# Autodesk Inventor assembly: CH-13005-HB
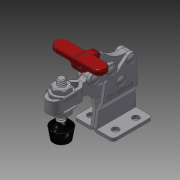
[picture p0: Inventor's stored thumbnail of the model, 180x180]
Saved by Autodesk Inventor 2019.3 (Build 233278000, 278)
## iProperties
Company: Î¢ÈíÖÐ¹ú
Created: 2012-09
Part Number: CH-13005-HB
Material: Ogólny
Description: STEP AP203
Document SubType Name: Assembly
Designer: CADENGINEERING4
Stock Number: DOCISK PIONOWY
Sending System: SolidWorks 2010
Preprocessor: SwSTEP 2.0
Title: CH-13005-HB.STEP
Author: Î¢ÈíÓÃ»§
Revision Number: ÈÎºÎ
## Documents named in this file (9)
- D:\Vault_2016\Projekty\Clamptek\STRONA\Vertical toggle clamp\CH-13005-HB\CH-13005-HB.iam
- D:\Vault_2016\Projekty\Clamptek\STRONA\Vertical toggle clamp\CH-13005-HB\CH-FW-100.ipt
- D:\Vault_2016\Projekty\Clamptek\STRONA\Vertical toggle clamp\CH-13005-HB\CH-13005-04 CONNECTING-PLATE.ipt
- D:\Vault_2016\Projekty\Clamptek\STRONA\Vertical toggle clamp\CH-13005-HB\CH-13005-05 .ipt
- D:\Vault_2016\Projekty\Clamptek\STRONA\Vertical toggle clamp\CH-13005-HB\CH-13005-02 U-BAR.ipt
- D:\Vault_2016\Projekty\Clamptek\STRONA\Vertical toggle clamp\CH-13005-HB\CH-FC-10138 Nut.ipt
- D:\Vault_2016\Projekty\Clamptek\STRONA\Vertical toggle clamp\CH-13005-HB\CH-13005-HB-01 FLANGED BASE.ipt
- D:\Vault_2016\Projekty\Clamptek\STRONA\Vertical toggle clamp\CH-13005-HB\CH-FC-10138 SPINDLE SUPPLIED.ipt
- D:\Vault_2016\Projekty\Clamptek\STRONA\Vertical toggle clamp\CH-13005-HB\CH-13005-03 T-HANDLE.ipt
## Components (14 placed, 14 different names)
1. CH-FW-100_1 — Zestawiające:20, Zestawiające:22, Zestawiające:23, Zestawiające:24, Zestawiające:25, Zestawiające:28, Kątowe:1
2. CH-13005-04 CONNECTING-PLATE_2 — Zestawiające:5, Zestawiające:6, Zestawiające:10, Zestawiające:15, Zestawiające:16
3. CH-13005-05 _3 — Zestawiające:12, Zestawiające:18
4. CH-13005-02 U-BAR_4 — Zestawiające:2, Zestawiające:4, Zestawiające:5, Zestawiające:7, Zestawiające:9, Zestawiające:10, Zestawiające:20, Zestawiające:21, Zestawiające:23, Zestawiające:24, Kątowe:1, Kątowe:2
5. CH-FC-10138 Nut_5 — Zestawiające:26, Zestawiające:27
6. CH-13005-HB-01 FLANGED BASE_6 — Zestawiające:1, Zestawiające:2, Zestawiające:7, Zestawiające:8, Zestawiające:11, Zestawiające:12, Zestawiające:17, Zestawiające:18, Zestawiające:19
7. CH-FW-100_7 — Zestawiające:21, Zestawiające:22, Zestawiające:26, Zestawiające:27, Równoległe:1, Kątowe:2
8. CH-13005-05 _8 — Zestawiające:11, Zestawiające:17
9. CH-13005-05 _9 — Zestawiające:13, Zestawiające:16
10. CH-FC-10138 Nut_10 — Zestawiające:25, Zestawiające:28, Zestawiające:29
11. CH-13005-05 _11 — Zestawiające:14, Zestawiające:15
12. CH-FC-10138 SPINDLE SUPPLIED_12 — Zestawiające:29, Równoległe:1
13. CH-13005-03 T-HANDLE_13 — Zestawiające:1, Zestawiające:3, Zestawiające:6, Zestawiające:8
14. CH-13005-04 CONNECTING-PLATE_14 — Zestawiające:3, Zestawiające:4, Zestawiające:9, Zestawiające:13, Zestawiające:14, Zestawiające:19
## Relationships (32: Mate 29, Angle 2, Flush 1)
- Zestawiające:1 [Mate]: CH-13005-HB-01 FLANGED BASE_6 ↔ CH-13005-03 T-HANDLE_13
- Zestawiające:2 [Mate]: CH-13005-02 U-BAR_4 ↔ CH-13005-HB-01 FLANGED BASE_6
- Zestawiające:3 [Mate]: CH-13005-03 T-HANDLE_13 ↔ CH-13005-04 CONNECTING-PLATE_14
- Zestawiające:4 [Mate]: CH-13005-02 U-BAR_4 ↔ CH-13005-04 CONNECTING-PLATE_14
- Zestawiające:5 [Mate]: CH-13005-04 CONNECTING-PLATE_2 ↔ CH-13005-02 U-BAR_4
- Zestawiające:6 [Mate]: CH-13005-04 CONNECTING-PLATE_2 ↔ CH-13005-03 T-HANDLE_13
- Zestawiające:7 [Mate]: CH-13005-02 U-BAR_4 ↔ CH-13005-HB-01 FLANGED BASE_6
- Zestawiające:8 [Mate]: CH-13005-HB-01 FLANGED BASE_6 ↔ CH-13005-03 T-HANDLE_13
- Zestawiające:9 [Mate]: CH-13005-02 U-BAR_4 ↔ CH-13005-04 CONNECTING-PLATE_14
- Zestawiające:10 [Mate]: CH-13005-04 CONNECTING-PLATE_2 ↔ CH-13005-02 U-BAR_4
- Zestawiające:11 [Mate]: CH-13005-HB-01 FLANGED BASE_6 ↔ CH-13005-05 _8
- Zestawiające:12 [Mate]: CH-13005-05 _3 ↔ CH-13005-HB-01 FLANGED BASE_6
- Zestawiające:13 [Mate]: CH-13005-05 _9 ↔ CH-13005-04 CONNECTING-PLATE_14
- Zestawiające:14 [Mate]: CH-13005-05 _11 ↔ CH-13005-04 CONNECTING-PLATE_14
- Zestawiające:15 [Mate]: CH-13005-04 CONNECTING-PLATE_2 ↔ CH-13005-05 _11
- Zestawiające:16 [Mate]: CH-13005-04 CONNECTING-PLATE_2 ↔ CH-13005-05 _9
- Zestawiające:17 [Mate]: CH-13005-HB-01 FLANGED BASE_6 ↔ CH-13005-05 _8
- Zestawiające:18 [Mate]: CH-13005-05 _3 ↔ CH-13005-HB-01 FLANGED BASE_6
- Zestawiające:19 [Mate]: CH-13005-HB-01 FLANGED BASE_6 ↔ CH-13005-04 CONNECTING-PLATE_14
- Zestawiające:20 [Mate]: CH-FW-100_1 ↔ CH-13005-02 U-BAR_4
- Zestawiające:21 [Mate]: CH-13005-02 U-BAR_4 ↔ CH-FW-100_7
- Zestawiające:22 [Mate]: CH-FW-100_1 ↔ CH-FW-100_7
- Zestawiające:23 [Mate]: CH-FW-100_1 ↔ CH-13005-02 U-BAR_4
- Zestawiające:24 [Mate]: CH-FW-100_1 ↔ CH-13005-02 U-BAR_4
- Zestawiające:25 [Mate]: CH-FW-100_1 ↔ CH-FC-10138 Nut_10
- Zestawiające:26 [Mate]: CH-FC-10138 Nut_5 ↔ CH-FW-100_7
- Zestawiające:27 [Mate]: CH-FC-10138 Nut_5 ↔ CH-FW-100_7
- Zestawiające:28 [Mate]: CH-FW-100_1 ↔ CH-FC-10138 Nut_10
- Zestawiające:29 [Mate]: CH-FC-10138 Nut_10 ↔ CH-FC-10138 SPINDLE SUPPLIED_12
- Równoległe:1 [Flush]: CH-FW-100_7 ↔ CH-FC-10138 SPINDLE SUPPLIED_12
- Kątowe:1 [Angle]: CH-FW-100_1 ↔ CH-13005-02 U-BAR_4
- Kątowe:2 [Angle]: CH-13005-02 U-BAR_4 ↔ CH-FW-100_7
